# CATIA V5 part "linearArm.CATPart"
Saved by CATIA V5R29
Part number: linearArm
Bounding box of the stored display mesh (mm): x -25 to 25, y -245 to 25, z -50 to 0
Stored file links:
  C:\Users\Administrator\Desktop\프로젝트\Gripper\linearArm.CATPart
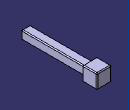
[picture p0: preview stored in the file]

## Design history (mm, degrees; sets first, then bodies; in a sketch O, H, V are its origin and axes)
Body1 (main body)
  Sketch1 on xy-plane, origin (0, 0, 0), H (0, -1, 0), V (-1, 0, 0)
    line L1 (25, 25) -> (25, -25)
    line L2 (25, -25) -> (-25, -25)
    line L3 (-25, -25) -> (-25, 25)
    line L4 (-25, 25) -> (25, 25)
    length L4 = 50
    distance L4 L2 = 50
    vertical: L1 V, L3 V
    horizontal: L2 H, L4 H
    equidistance: L1 L3 O, L2 L4 O
  Pad1: profile Sketch1, direction (0, 0, -1), length 50
  Sketch2 on face of Pad1 from Sketch1.L1, origin (0, -25, 0), H (0, 0, 1), V (-1, 0, 0)
    line L1 (-40, 15) -> (-10, 15)
    line L2 (-10, 15) -> (-10, -15)
    line L3 (-10, -15) -> (-40, -15)
    line L4 (-40, -15) -> (-40, 15)
    reference projected line E1 (0, 25) -> (-50, 25) from edge [face of Pad1 from Sketch1.L4 | face of Pad1 from Sketch1.L1]
    reference projected line E2 (-50, -25) -> (-50, 25) from edge [face of Pad1 from Sketch1.L1 | end face of Pad1]
    length L1 = 30
    length L4 = 30
    distance L1 E1 = 10
    distance L4 E2 = 10
    horizontal: L1 H, L3 H
    vertical: L2 V, L4 V
  Pad2: profile Sketch2, direction (0, -1, 0), length 220
  Fillet1: radius 3, on face of Pad2 from Sketch2.L1; face of Pad2 from Sketch2.L4; face of Pad2 from Sketch2.L3; face of Pad2 from Sketch2.L2; end face of Pad1; face of Pad1 from Sketch1.L4; face of Pad1 from Sketch1.L3; face of Pad1 from Sketch1.L2; face of Pad1 from Sketch1.L1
